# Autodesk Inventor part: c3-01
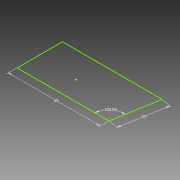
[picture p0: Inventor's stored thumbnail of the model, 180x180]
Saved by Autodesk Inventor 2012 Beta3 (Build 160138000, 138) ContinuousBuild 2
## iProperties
Created: 2010-11
Part Number: c3-01
Material: Default
Document SubType Name: Modeling
Designer: Beta-8540w
Density: 1 g/cm^3
Author: Beta-8540w
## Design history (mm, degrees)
sketch "Sketch1"
  geometry: L1 (-25.902, -12.554)-(34.098, -12.554); L2 (34.098, -12.554)-(39.308, 16.99); L3 (39.308, 16.99)-(-25.902, 16.99); L4 (-25.902, 16.99)-(-25.902, -12.554); 1 further point
  constraints: 8 end point, 1 horizontal, 1 parallel, 1 perpendicular
  dimensions: "d0" = 60 dimension on point (0, 0) L1.start L1.end L1 L2.end L2 L3.end L3 L4; "d0" = 60 distance of L1.start L1.end; "d1" = 30 distance of L1.end L2.end; "d2" = 100 deg angle of L2 L1
